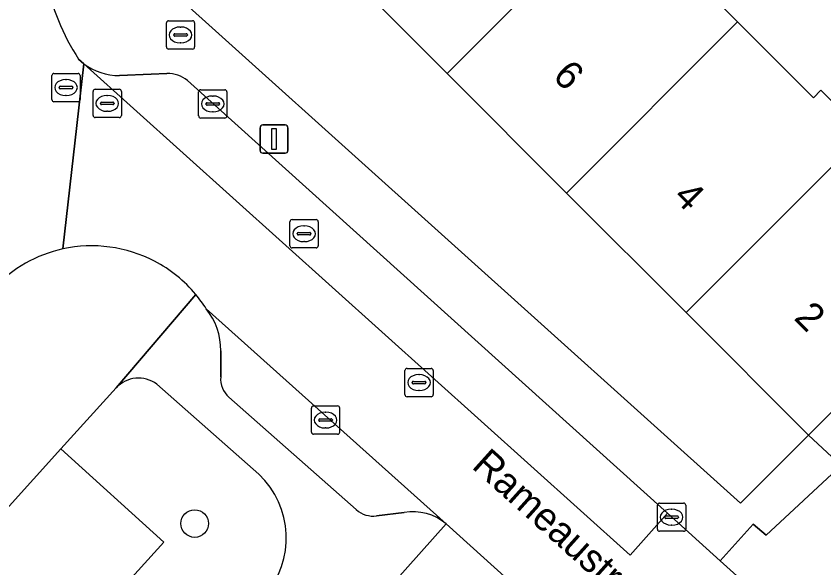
# Model space of a CAD drawing. Extents: x 159039 to 160102, y 381214 to 382524.
# Drawn here: x 159543.52 to 159572.13, y 381802.95 to 381822.48 of the extents above; entities that cross this region are included whole.
import ezdxf

# ---------------------------------------------------------------- set-up
doc = ezdxf.new("R2010")
doc.units = 0
for name, color, linetype in [('IMGEO_Boom', 7, 'Continuous'), ('IMGEO_Brandkraan', 7, 'Continuous'), ('IMGEO_Erf', 7, 'Continuous'), ('IMGEO_Groenvoorziening', 7, 'Continuous'), ('IMGEO_Kolk', 7, 'Continuous'), ('IMGEO_Lichtmast', 7, 'Continuous'), ('IMGEO_Openbare_ruimte_label', 7, 'Continuous'), ('IMGEO_Pand', 7, 'Continuous'), ('IMGEO_Pand_nummerreeks', 7, 'Continuous'), ('IMGEO_Parkeervlak_open', 7, 'Continuous'), ('IMGEO_Rijbaan_lokaal_open', 7, 'Continuous'), ('IMGEO_Rioolput', 7, 'Continuous'), ('IMGEO_Voetpad_open', 7, 'Continuous')]:
    doc.layers.add(name, color=color, linetype=linetype)

msp = doc.modelspace()

# ---------------------------------------------------------------- linework, layer by layer
at = {"layer": 'IMGEO_Boom'}
msp.add_circle((159549.845, 381804.514), 0.489, dxfattribs=at)
at = {"layer": 'IMGEO_Brandkraan'}
for p, q in [((159548.842, 381821.386), (159548.842, 381822.238)), ((159548.917, 381822.312), (159549.769, 381822.312)), ((159549.843, 381822.238), (159549.843, 381821.386)), ((159549.33, 381822.092), (159549.355, 381822.092)), ((159549.101, 381821.806), (159549.101, 381821.818)), ((159549.539, 381821.769), (159549.141, 381821.769)), ((159549.144, 381821.855), (159549.542, 381821.855)), ((159549.585, 381821.818), (159549.585, 381821.806)), ((159549.353, 381821.532), (159549.328, 381821.532)), ((159549.769, 381821.312), (159548.917, 381821.312))]:
    msp.add_line(p, q, dxfattribs=at)
for points in [[(159548.842, 381821.386), (159548.842, 381822.238)], [(159548.917, 381822.312), (159549.769, 381822.312)], [(159549.843, 381822.238), (159549.843, 381821.386)], [(159549.769, 381821.312), (159548.917, 381821.312)]]:
    msp.add_lwpolyline(points, dxfattribs=at)
for centre, radius, start, end in [((159548.919, 381822.236), 0.0765, 91.552, 178.448), ((159548.919, 381822.236), 0.0765, 91.552, 178.448), ((159549.767, 381822.236), 0.0765, 1.552, 88.448), ((159549.767, 381822.236), 0.0765, 1.552, 88.448), ((159549.141, 381821.815), 0.0403, 85.8775, 175.7526), ((159549.138, 381821.805), 0.0366, 178.938, 274.7102), ((159549.542, 381821.812), 0.043, 264.8664, 352.4533), ((159549.546, 381821.817), 0.0386, 1.7309, 96.639), ((159548.919, 381821.388), 0.0765, 181.552, 268.448), ((159548.919, 381821.388), 0.0765, 181.552, 268.448), ((159549.767, 381821.388), 0.0765, 271.552, 358.448), ((159549.767, 381821.388), 0.0765, 271.552, 358.448)]:
    msp.add_arc(centre, radius, start, end, dxfattribs=at)
for centre, major_axis, ratio, start_param, end_param in [((159549.329, 381821.812), (-0.387, 0.002), 0.722429, 4.712389, 7.853982), ((159549.354, 381821.812), (-0.39, 0.002), 0.717154, 1.570796, 4.712389)]:
    msp.add_ellipse(centre, major_axis=major_axis, ratio=ratio, start_param=start_param, end_param=end_param, dxfattribs=at)
at = {"layer": 'IMGEO_Erf'}
msp.add_lwpolyline([(159569.175, 381805.236), (159571.586, 381807.648), (159567.25, 381811.984), (159563.018, 381816.215), (159558.787, 381820.446), (159554.556, 381824.678), (159550.288, 381828.945), (159548.468, 381827.062), (159548.229, 381824.079)], close=True, dxfattribs=at)
for points in [[(159566.628, 381824.722), (159569.076, 381822.274), (159571.764, 381819.587), (159572.031, 381819.854), (159573.578, 381818.308)], [(159573.722, 381809.785), (159571.586, 381807.648), (159572.743, 381806.566)]]:
    msp.add_lwpolyline(points, dxfattribs=at)
at = {"layer": 'IMGEO_Groenvoorziening'}
for points in [[(159552.111, 381806.258), (159548.503, 381809.449)], [(159547.059, 381809.314), (159545.108, 381807.153)], [(159545.108, 381807.153), (159548.757, 381803.854), (159534.941, 381788.628)]]:
    msp.add_lwpolyline(points, dxfattribs=at)
msp.add_lwpolyline([(159534.941, 381788.628), (159548.757, 381803.854), (159545.108, 381807.153), (159531.326, 381791.884)], close=True, dxfattribs=at)
for centre, radius, start, end in [((159547.856, 381808.577), 1.086, 53.4291, 137.2531), ((159550.008, 381804.002), 3.085, 318.387, 47.0125)]:
    msp.add_arc(centre, radius, start, end, dxfattribs=at)
at = {"layer": 'IMGEO_Kolk'}
for p, q in [((159549.985, 381818.943), (159549.985, 381819.795)), ((159550.06, 381819.869), (159550.912, 381819.869)), ((159550.473, 381819.649), (159550.498, 381819.649)), ((159550.986, 381819.795), (159550.986, 381818.943)), ((159550.244, 381819.363), (159550.244, 381819.375)), ((159550.287, 381819.412), (159550.685, 381819.412)), ((159550.728, 381819.375), (159550.728, 381819.363)), ((159550.682, 381819.326), (159550.284, 381819.326)), ((159550.496, 381819.089), (159550.471, 381819.089)), ((159550.912, 381818.869), (159550.06, 381818.869)), ((159553.979, 381807.751), (159553.979, 381808.603)), ((159554.054, 381808.677), (159554.906, 381808.677)), ((159554.98, 381808.603), (159554.98, 381807.751)), ((159554.281, 381808.22), (159554.679, 381808.22)), ((159554.467, 381808.457), (159554.492, 381808.457)), ((159554.238, 381808.171), (159554.238, 381808.183)), ((159554.676, 381808.134), (159554.278, 381808.134)), ((159554.722, 381808.183), (159554.722, 381808.171)), ((159554.906, 381807.677), (159554.054, 381807.677)), ((159554.49, 381807.897), (159554.465, 381807.897)), ((159566.238, 381804.313), (159566.238, 381805.165)), ((159566.313, 381805.239), (159567.165, 381805.239)), ((159567.239, 381805.165), (159567.239, 381804.313)), ((159566.54, 381804.782), (159566.938, 381804.782)), ((159566.726, 381805.019), (159566.751, 381805.019)), ((159566.497, 381804.733), (159566.497, 381804.745)), ((159566.935, 381804.696), (159566.537, 381804.696)), ((159566.981, 381804.745), (159566.981, 381804.733)), ((159567.165, 381804.239), (159566.313, 381804.239)), ((159566.749, 381804.459), (159566.724, 381804.459))]:
    msp.add_line(p, q, dxfattribs=at)
for points in [[(159549.985, 381818.943), (159549.985, 381819.795)], [(159550.06, 381819.869), (159550.912, 381819.869)], [(159550.986, 381819.795), (159550.986, 381818.943)], [(159550.912, 381818.869), (159550.06, 381818.869)], [(159553.979, 381807.751), (159553.979, 381808.603)], [(159554.054, 381808.677), (159554.906, 381808.677)], [(159554.98, 381808.603), (159554.98, 381807.751)], [(159554.906, 381807.677), (159554.054, 381807.677)], [(159566.238, 381804.313), (159566.238, 381805.165)], [(159566.313, 381805.239), (159567.165, 381805.239)], [(159567.239, 381805.165), (159567.239, 381804.313)], [(159567.165, 381804.239), (159566.313, 381804.239)]]:
    msp.add_lwpolyline(points, dxfattribs=at)
for centre, radius, start, end in [((159550.062, 381819.793), 0.0765, 91.552, 178.448), ((159550.062, 381819.793), 0.0765, 91.552, 178.448), ((159550.91, 381819.793), 0.0765, 1.552, 88.448), ((159550.91, 381819.793), 0.0765, 1.552, 88.448), ((159550.284, 381819.372), 0.0403, 85.8775, 175.7526), ((159550.281, 381819.362), 0.0366, 178.938, 274.7102), ((159550.685, 381819.369), 0.043, 264.8664, 352.4533), ((159550.689, 381819.374), 0.0386, 1.7309, 96.639), ((159550.062, 381818.945), 0.0765, 181.552, 268.448), ((159550.062, 381818.945), 0.0765, 181.552, 268.448), ((159550.91, 381818.945), 0.0765, 271.552, 358.448), ((159550.91, 381818.945), 0.0765, 271.552, 358.448), ((159554.056, 381808.601), 0.0765, 91.552, 178.448), ((159554.056, 381808.601), 0.0765, 91.552, 178.448), ((159554.904, 381808.601), 0.0765, 1.552, 88.448), ((159554.904, 381808.601), 0.0765, 1.552, 88.448), ((159554.278, 381808.18), 0.0403, 85.8775, 175.7526), ((159554.683, 381808.182), 0.0386, 1.7309, 96.639), ((159554.275, 381808.17), 0.0366, 178.938, 274.7102), ((159554.679, 381808.177), 0.043, 264.8664, 352.4533), ((159554.056, 381807.753), 0.0765, 181.552, 268.448), ((159554.056, 381807.753), 0.0765, 181.552, 268.448), ((159554.904, 381807.753), 0.0765, 271.552, 358.448), ((159554.904, 381807.753), 0.0765, 271.552, 358.448), ((159566.315, 381805.163), 0.0765, 91.552, 178.448), ((159566.315, 381805.163), 0.0765, 91.552, 178.448), ((159567.163, 381805.163), 0.0765, 1.552, 88.448), ((159567.163, 381805.163), 0.0765, 1.552, 88.448), ((159566.537, 381804.742), 0.0403, 85.8775, 175.7526), ((159566.942, 381804.744), 0.0386, 1.7309, 96.639), ((159566.534, 381804.732), 0.0366, 178.938, 274.7102), ((159566.938, 381804.739), 0.043, 264.8664, 352.4533), ((159566.315, 381804.315), 0.0765, 181.552, 268.448), ((159566.315, 381804.315), 0.0765, 181.552, 268.448), ((159567.163, 381804.315), 0.0765, 271.552, 358.448), ((159567.163, 381804.315), 0.0765, 271.552, 358.448)]:
    msp.add_arc(centre, radius, start, end, dxfattribs=at)
for centre, major_axis, ratio, start_param, end_param in [((159550.472, 381819.369), (-0.387, 0.002), 0.722429, 4.712389, 7.853982), ((159550.497, 381819.369), (-0.39, 0.002), 0.717154, 1.570796, 4.712389), ((159554.466, 381808.177), (-0.387, 0.002), 0.722429, 4.712389, 7.853982), ((159554.491, 381808.177), (-0.39, 0.002), 0.717154, 1.570796, 4.712389), ((159566.725, 381804.739), (-0.387, 0.002), 0.722429, 4.712389, 7.853982), ((159566.75, 381804.739), (-0.39, 0.002), 0.717154, 1.570796, 4.712389)]:
    msp.add_ellipse(centre, major_axis=major_axis, ratio=ratio, start_param=start_param, end_param=end_param, dxfattribs=at)
at = {"layer": 'IMGEO_Lichtmast'}
for p, q in [((159552.158, 381817.725), (159552.158, 381818.525)), ((159552.158, 381818.525), (159552.158, 381817.725)), ((159552.258, 381818.625), (159553.048, 381818.625)), ((159553.048, 381818.625), (159552.258, 381818.625)), ((159553.148, 381818.525), (159553.148, 381817.725)), ((159553.148, 381817.725), (159553.148, 381818.525)), ((159553.048, 381817.625), (159552.258, 381817.625)), ((159552.258, 381817.625), (159553.048, 381817.625))]:
    msp.add_line(p, q, dxfattribs=at)
msp.add_lwpolyline([(159552.578, 381818.5), (159552.728, 381818.5), (159552.728, 381817.75), (159552.578, 381817.75), (159552.578, 381818.5)], dxfattribs=at)
for centre, start, end in [((159552.258, 381818.525), 90, 180), ((159552.258, 381818.525), 90, 180), ((159553.048, 381818.525), 0, 90), ((159553.048, 381818.525), 360, 90), ((159552.258, 381817.725), 180, 270), ((159552.258, 381817.725), 180, 270), ((159553.048, 381817.725), 270, 0), ((159553.048, 381817.725), 270, 0)]:
    msp.add_arc(centre, 0.1, start, end, dxfattribs=at)
at = {"layer": 'IMGEO_Pand'}
for points in [[(159560.617, 381830.741), (159554.556, 381824.678), (159558.787, 381820.446), (159565.021, 381826.682), (159563.497, 381828.206), (159563.325, 381828.034)], [(159565.021, 381826.682), (159558.787, 381820.446), (159563.018, 381816.215), (159569.076, 381822.274), (159566.628, 381824.722), (159566.805, 381824.898)], [(159567.25, 381811.984), (159573.474, 381818.21), (159573.578, 381818.308), (159572.031, 381819.854), (159571.764, 381819.587), (159569.076, 381822.274), (159563.018, 381816.215)], [(159567.25, 381811.984), (159571.586, 381807.648), (159573.722, 381809.785), (159573.857, 381809.65), (159577.393, 381813.186), (159577.789, 381813.582), (159575.152, 381816.218), (159575.41, 381816.476), (159573.578, 381818.308), (159573.474, 381818.21)]]:
    msp.add_lwpolyline(points, close=True, dxfattribs=at)
at = {"layer": 'IMGEO_Parkeervlak_open'}
for points in [[(159545.921, 381820.792), (159565.267, 381803.393), (159566.59, 381804.886), (159549.587, 381820.194)], [(159548.861, 381820.445), (159548.298, 381820.421), (159547.18, 381820.373)], [(159558.749, 381804.5), (159550.255, 381812.115)], [(159550.766, 381810.633), (159550.766, 381809.705)], [(159551.058, 381808.987), (159555.57, 381805.009)], [(159556.29, 381804.79), (159557.266, 381804.901)]]:
    msp.add_lwpolyline(points, dxfattribs=at)
for centre, radius, start, end in [((159547.17, 381822.445), 2.072, 232.9158, 270.2689), ((159548.888, 381819.348), 1.097, 50.4378, 91.4186), ((159548.421, 381810.654), 2.345, 359.4967, 38.5521), ((159551.6, 381809.626), 0.837, 174.5624, 229.6993), ((159556.154, 381805.635), 0.856, 226.9984, 279.1656), ((159557.584, 381803.134), 1.795, 49.5403, 100.1981)]:
    msp.add_arc(centre, radius, start, end, dxfattribs=at)
at = {"layer": 'IMGEO_Rijbaan_lokaal_open'}
for points in [[(159545.171, 381814.234), (159545.921, 381820.792)], [(159568.463, 381803.199), (159566.59, 381804.886), (159565.267, 381803.393), (159545.921, 381820.792), (159545.171, 381814.234)], [(159545.921, 381820.792), (159545.734, 381820.952)], [(159550.255, 381812.115), (159558.749, 381804.5), (159570.287, 381794.097), (159577.561, 381787.517), (159590.415, 381775.929)], [(159593.184, 381778.233), (159593.076, 381778.33), (159581.268, 381788.98), (159582.613, 381790.494), (159574.952, 381797.387), (159572.145, 381799.881), (159568.463, 381803.199)]]:
    msp.add_lwpolyline(points, dxfattribs=at)
msp.add_lwpolyline([(159575.626, 381804.406), (159573.086, 381806.886), (159572.743, 381806.566), (159570.095, 381804.098), (159569.624, 381804.489), (159568.463, 381803.199), (159572.145, 381799.881), (159572.457, 381800.224), (159573.253, 381801.12), (159572.82, 381801.518), (159573.302, 381802.014)], close=True, dxfattribs=at)
for centre, radius, start, end in [((159552.275, 381825.26), 7.832, 190.7342, 213.367), ((159546.208, 381809.543), 4.804, 102.468, 136.4034), ((159546.198, 381809.525), 4.82, 62.5216, 102.3052), ((159546.2, 381809.545), 4.801, 39.8923, 62.4353), ((159546.109, 381809.483), 4.911, 32.4107, 39.7645)]:
    msp.add_arc(centre, radius, start, end, dxfattribs=at)
at = {"layer": 'IMGEO_Rioolput'}
for p, q in [((159544.785, 381819.523), (159544.785, 381820.375)), ((159544.86, 381820.449), (159545.712, 381820.449)), ((159545.273, 381820.229), (159545.298, 381820.229)), ((159545.786, 381820.375), (159545.786, 381819.523)), ((159545.044, 381819.943), (159545.044, 381819.955)), ((159545.087, 381819.992), (159545.485, 381819.992)), ((159545.528, 381819.955), (159545.528, 381819.943)), ((159545.482, 381819.906), (159545.084, 381819.906)), ((159545.296, 381819.669), (159545.271, 381819.669)), ((159546.246, 381818.962), (159546.246, 381819.814)), ((159546.321, 381819.888), (159547.173, 381819.888)), ((159546.734, 381819.668), (159546.759, 381819.668)), ((159547.247, 381819.814), (159547.247, 381818.962)), ((159545.712, 381819.449), (159544.86, 381819.449)), ((159546.505, 381819.382), (159546.505, 381819.394)), ((159546.548, 381819.431), (159546.946, 381819.431)), ((159546.989, 381819.394), (159546.989, 381819.382)), ((159546.943, 381819.345), (159546.545, 381819.345)), ((159546.757, 381819.108), (159546.732, 381819.108)), ((159547.173, 381818.888), (159546.321, 381818.888)), ((159553.219, 381814.348), (159553.219, 381815.2)), ((159553.294, 381815.274), (159554.146, 381815.274)), ((159554.22, 381815.2), (159554.22, 381814.348)), ((159553.478, 381814.768), (159553.478, 381814.78)), ((159553.521, 381814.817), (159553.919, 381814.817)), ((159553.707, 381815.054), (159553.732, 381815.054)), ((159553.962, 381814.78), (159553.962, 381814.768)), ((159553.916, 381814.731), (159553.518, 381814.731)), ((159553.73, 381814.494), (159553.705, 381814.494)), ((159554.146, 381814.274), (159553.294, 381814.274)), ((159557.292, 381809.079), (159557.292, 381809.931)), ((159557.367, 381810.005), (159558.219, 381810.005)), ((159558.293, 381809.931), (159558.293, 381809.079)), ((159557.78, 381809.785), (159557.805, 381809.785)), ((159557.551, 381809.499), (159557.551, 381809.511)), ((159557.989, 381809.462), (159557.591, 381809.462)), ((159557.594, 381809.548), (159557.992, 381809.548)), ((159558.035, 381809.511), (159558.035, 381809.499)), ((159557.803, 381809.225), (159557.778, 381809.225)), ((159558.219, 381809.005), (159557.367, 381809.005))]:
    msp.add_line(p, q, dxfattribs=at)
for points in [[(159544.785, 381819.523), (159544.785, 381820.375)], [(159544.86, 381820.449), (159545.712, 381820.449)], [(159545.786, 381820.375), (159545.786, 381819.523)], [(159546.246, 381818.962), (159546.246, 381819.814)], [(159546.321, 381819.888), (159547.173, 381819.888)], [(159547.247, 381819.814), (159547.247, 381818.962)], [(159545.712, 381819.449), (159544.86, 381819.449)], [(159547.173, 381818.888), (159546.321, 381818.888)], [(159553.219, 381814.348), (159553.219, 381815.2)], [(159553.294, 381815.274), (159554.146, 381815.274)], [(159554.22, 381815.2), (159554.22, 381814.348)], [(159554.146, 381814.274), (159553.294, 381814.274)], [(159557.292, 381809.079), (159557.292, 381809.931)], [(159557.367, 381810.005), (159558.219, 381810.005)], [(159558.293, 381809.931), (159558.293, 381809.079)], [(159558.219, 381809.005), (159557.367, 381809.005)]]:
    msp.add_lwpolyline(points, dxfattribs=at)
for centre, radius, start, end in [((159544.862, 381820.373), 0.0765, 91.552, 178.448), ((159544.862, 381820.373), 0.0765, 91.552, 178.448), ((159545.71, 381820.373), 0.0765, 1.552, 88.448), ((159545.71, 381820.373), 0.0765, 1.552, 88.448), ((159545.084, 381819.952), 0.0403, 85.8775, 175.7526), ((159545.081, 381819.942), 0.0366, 178.938, 274.7102), ((159545.485, 381819.949), 0.043, 264.8664, 352.4533), ((159545.489, 381819.954), 0.0386, 1.7309, 96.639), ((159546.323, 381819.812), 0.0765, 91.552, 178.448), ((159546.323, 381819.812), 0.0765, 91.552, 178.448), ((159547.171, 381819.812), 0.0765, 1.552, 88.448), ((159547.171, 381819.812), 0.0765, 1.552, 88.448), ((159544.862, 381819.525), 0.0765, 181.552, 268.448), ((159544.862, 381819.525), 0.0765, 181.552, 268.448), ((159545.71, 381819.525), 0.0765, 271.552, 358.448), ((159545.71, 381819.525), 0.0765, 271.552, 358.448), ((159546.545, 381819.391), 0.0403, 85.8775, 175.7526), ((159546.542, 381819.381), 0.0366, 178.938, 274.7102), ((159546.946, 381819.388), 0.043, 264.8664, 352.4533), ((159546.95, 381819.393), 0.0386, 1.7309, 96.639), ((159546.323, 381818.964), 0.0765, 181.552, 268.448), ((159546.323, 381818.964), 0.0765, 181.552, 268.448), ((159547.171, 381818.964), 0.0765, 271.552, 358.448), ((159547.171, 381818.964), 0.0765, 271.552, 358.448), ((159553.296, 381815.198), 0.0765, 91.552, 178.448), ((159553.296, 381815.198), 0.0765, 91.552, 178.448), ((159554.144, 381815.198), 0.0765, 1.552, 88.448), ((159554.144, 381815.198), 0.0765, 1.552, 88.448), ((159553.518, 381814.777), 0.0403, 85.8775, 175.7526), ((159553.923, 381814.779), 0.0386, 1.7309, 96.639), ((159553.515, 381814.767), 0.0366, 178.938, 274.7102), ((159553.919, 381814.774), 0.043, 264.8664, 352.4533), ((159553.296, 381814.35), 0.0765, 181.552, 268.448), ((159553.296, 381814.35), 0.0765, 181.552, 268.448), ((159554.144, 381814.35), 0.0765, 271.552, 358.448), ((159554.144, 381814.35), 0.0765, 271.552, 358.448), ((159557.369, 381809.929), 0.0765, 91.552, 178.448), ((159557.369, 381809.929), 0.0765, 91.552, 178.448), ((159558.217, 381809.929), 0.0765, 1.552, 88.448), ((159558.217, 381809.929), 0.0765, 1.552, 88.448), ((159557.591, 381809.508), 0.0403, 85.8775, 175.7526), ((159557.588, 381809.498), 0.0366, 178.938, 274.7102), ((159557.992, 381809.505), 0.043, 264.8664, 352.4533), ((159557.996, 381809.51), 0.0386, 1.7309, 96.639), ((159557.369, 381809.081), 0.0765, 181.552, 268.448), ((159557.369, 381809.081), 0.0765, 181.552, 268.448), ((159558.217, 381809.081), 0.0765, 271.552, 358.448), ((159558.217, 381809.081), 0.0765, 271.552, 358.448)]:
    msp.add_arc(centre, radius, start, end, dxfattribs=at)
for centre, major_axis, ratio, start_param, end_param in [((159545.272, 381819.949), (-0.387, 0.002), 0.722429, 4.712389, 7.853982), ((159545.297, 381819.949), (-0.39, 0.002), 0.717154, 1.570796, 4.712389), ((159546.733, 381819.388), (-0.387, 0.002), 0.722429, 4.712389, 7.853982), ((159546.758, 381819.388), (-0.39, 0.002), 0.717154, 1.570796, 4.712389), ((159553.706, 381814.774), (-0.387, 0.002), 0.722429, 4.712389, 7.853982), ((159553.731, 381814.774), (-0.39, 0.002), 0.717154, 1.570796, 4.712389), ((159557.779, 381809.505), (-0.387, 0.002), 0.722429, 4.712389, 7.853982), ((159557.804, 381809.505), (-0.39, 0.002), 0.717154, 1.570796, 4.712389)]:
    msp.add_ellipse(centre, major_axis=major_axis, ratio=ratio, start_param=start_param, end_param=end_param, dxfattribs=at)
at = {"layer": 'IMGEO_Voetpad_open'}
for points in [[(159549.587, 381820.194), (159566.59, 381804.886), (159568.463, 381803.199), (159569.624, 381804.489), (159570.095, 381804.098), (159572.743, 381806.566), (159571.586, 381807.648), (159569.175, 381805.236), (159548.229, 381824.079)], [(159545.734, 381820.952), (159545.921, 381820.792)], [(159547.18, 381820.373), (159548.298, 381820.421), (159548.861, 381820.445)], [(159514.337, 381771.053), (159516.427, 381773.369), (159531.315, 381789.859), (159534.063, 381787.364), (159536.857, 381784.828), (159537.894, 381785.968), (159534.941, 381788.628), (159531.326, 381791.884), (159545.108, 381807.153), (159547.059, 381809.314), (159549.884, 381812.624)], [(159549.884, 381812.624), (159547.059, 381809.314)], [(159550.766, 381809.705), (159550.766, 381810.633)], [(159548.503, 381809.449), (159552.111, 381806.258)], [(159555.57, 381805.009), (159551.058, 381808.987)], [(159557.266, 381804.901), (159556.29, 381804.79)], [(159517.222, 381767.108), (159514.996, 381764.721), (159519.551, 381760.734), (159519.855, 381761.602), (159556.91, 381802.444), (159558.749, 381804.5)], [(159558.749, 381804.5), (159556.91, 381802.444)], [(159590.415, 381775.929), (159577.561, 381787.517), (159570.287, 381794.097), (159558.749, 381804.5)]]:
    msp.add_lwpolyline(points, dxfattribs=at)
for centre, radius, start, end in [((159552.275, 381825.26), 7.832, 190.7342, 213.367), ((159547.17, 381822.445), 2.072, 232.9158, 270.2689), ((159548.888, 381819.348), 1.097, 50.4378, 91.4186), ((159546.208, 381809.543), 4.804, 102.468, 136.4034), ((159546.198, 381809.525), 4.82, 62.5216, 102.3052), ((159546.2, 381809.545), 4.801, 39.8923, 62.4353), ((159546.109, 381809.483), 4.911, 32.4107, 39.7645), ((159548.421, 381810.654), 2.345, 359.4967, 38.5521), ((159547.856, 381808.577), 1.086, 53.4291, 137.2531), ((159551.6, 381809.626), 0.837, 174.5624, 229.6993), ((159550.008, 381804.002), 3.085, 318.387, 47.0125), ((159556.154, 381805.635), 0.856, 226.9984, 279.1656), ((159557.584, 381803.134), 1.795, 49.5403, 100.1981)]:
    msp.add_arc(centre, radius, start, end, dxfattribs=at)

# ---------------------------------------------------------------- texts
at = {"layer": 'IMGEO_Openbare_ruimte_label'}
msp.add_text('Rameaustraat', height=1, rotation=318.0383, dxfattribs=at).set_placement((159559.622, 381806.503))
at = {"layer": 'IMGEO_Pand_nummerreeks'}
for s, p in [('6', (159562.488, 381820.309)), ('4', (159566.762, 381816.035)), ('2', (159571.035, 381811.762))]:
    msp.add_text(s, height=1, rotation=315.0013, dxfattribs=at).set_placement(p)

doc.saveas('drawing.dxf')
